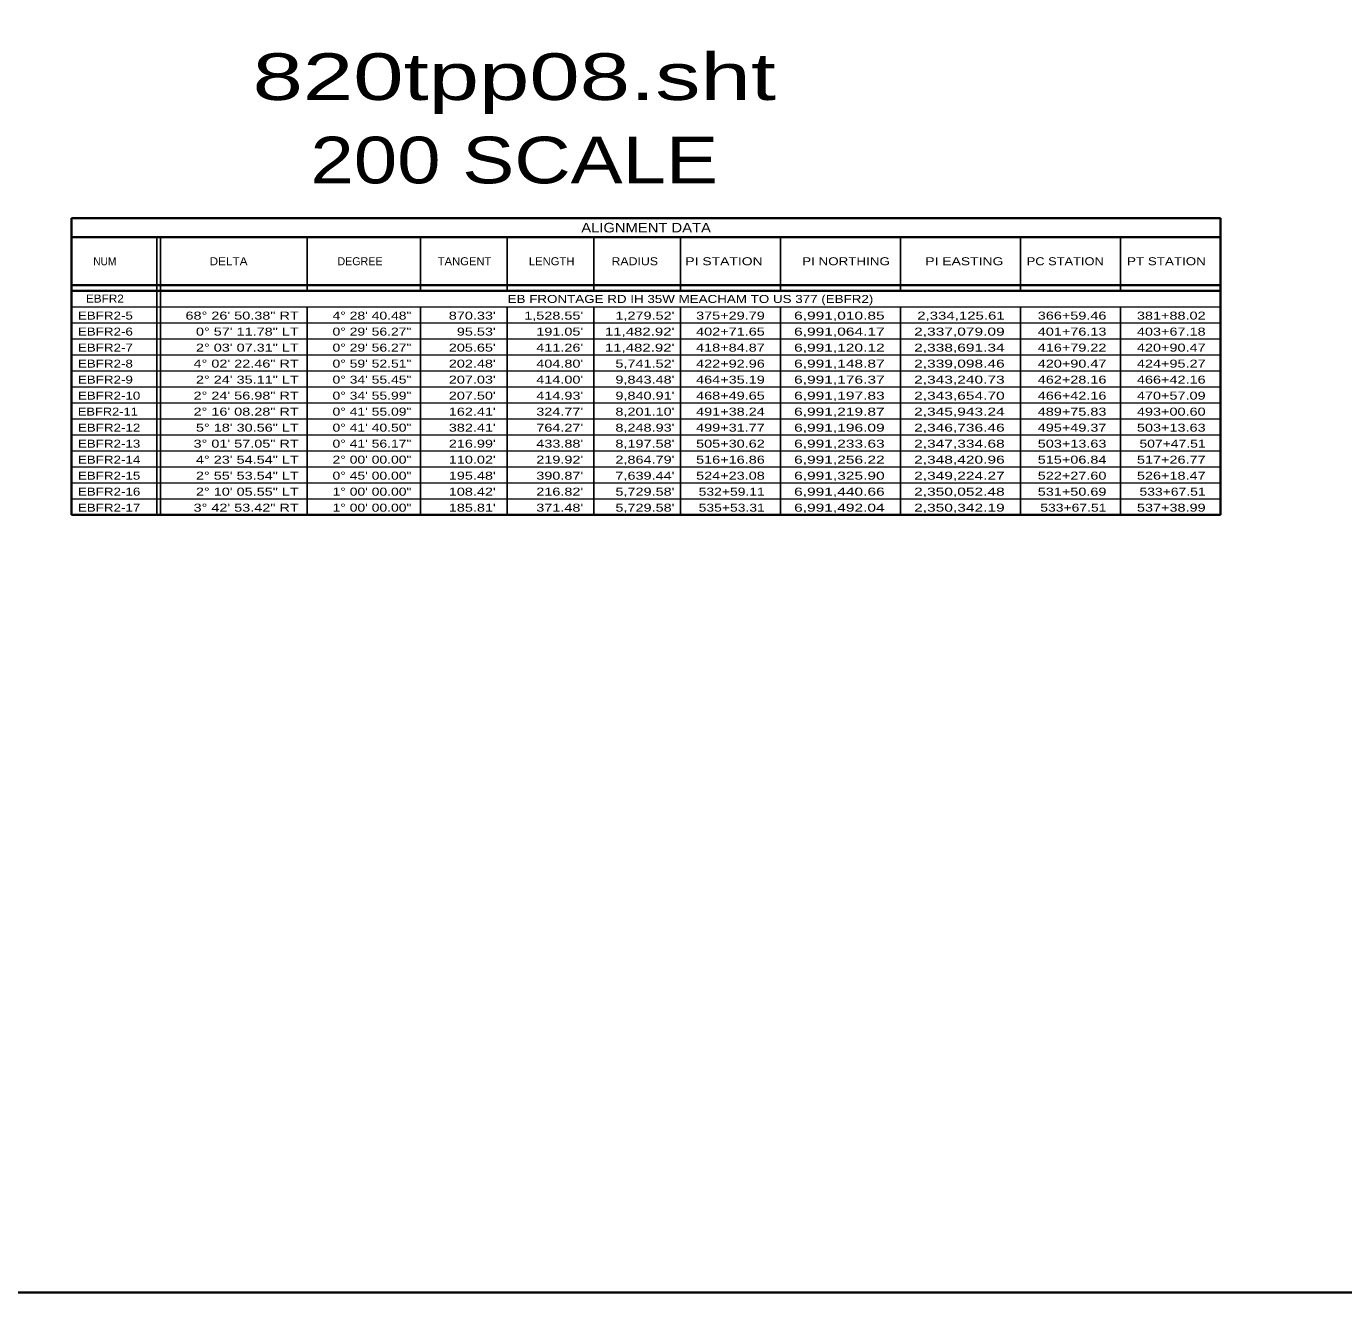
# Model space of a CAD drawing. Extents: x 1953053 to 1967065, y 7363860 to 7371201.
# Drawn here: x 1955866 to 1957841, y 7363860 to 7365759 of the extents above; entities that cross this region are included whole.
import ezdxf
from ezdxf.enums import TextEntityAlignment as Align

# ---------------------------------------------------------------- set-up
doc = ezdxf.new("R2010")
doc.units = 0
doc.header["$LTSCALE"] = 4.8
doc.layers.add('10', color=7, linetype='Continuous')
doc.layers.add('12', color=7, linetype='Continuous', lineweight=25)
doc.layers.add('62', color=7, linetype='Continuous', lineweight=35)

msp = doc.modelspace()

# ---------------------------------------------------------------- linework, layer by layer
at = {"layer": '12', "lineweight": 35}
for p, q in [((1957656.717, 7365471.266), (1955933.385, 7365471.266)), ((1955933.385, 7365471.266), (1955933.385, 7365026.133)), ((1957656.717, 7365026.133), (1957656.717, 7365471.266)), ((1955933.385, 7365442.466), (1957656.717, 7365442.466)), ((1955933.385, 7365370.466), (1957656.717, 7365370.466)), ((1955933.385, 7365362.133), (1957656.717, 7365362.133)), ((1955933.385, 7365026.133), (1957656.717, 7365026.133))]:
    msp.add_line(p, q, dxfattribs=at)
at = {"layer": '12'}
for p, q in [((1956061.23, 7365442.466), (1956061.23, 7365026.133)), ((1956066.717, 7365442.466), (1956066.717, 7365026.133)), ((1956286.717, 7365442.466), (1956286.717, 7365362.133)), ((1956456.717, 7365442.466), (1956456.717, 7365362.133)), ((1956586.717, 7365442.466), (1956586.717, 7365362.133)), ((1956716.717, 7365442.466), (1956716.717, 7365362.133)), ((1956846.717, 7365442.466), (1956846.717, 7365362.133)), ((1956996.717, 7365442.466), (1956996.717, 7365362.133)), ((1957176.717, 7365442.466), (1957176.717, 7365362.133)), ((1957356.717, 7365442.466), (1957356.717, 7365362.133)), ((1957506.717, 7365442.466), (1957506.717, 7365362.133)), ((1956061.23, 7365420.866), (1956061.23, 7365144.913)), ((1956286.717, 7365338.133), (1956286.717, 7365026.133)), ((1956456.717, 7365338.133), (1956456.717, 7365026.133)), ((1956586.717, 7365338.133), (1956586.717, 7365026.133)), ((1956716.717, 7365338.133), (1956716.717, 7365026.133)), ((1956846.717, 7365338.133), (1956846.717, 7365026.133)), ((1956996.717, 7365338.133), (1956996.717, 7365026.133)), ((1957176.717, 7365338.133), (1957176.717, 7365026.133)), ((1957356.717, 7365338.133), (1957356.717, 7365026.133)), ((1957506.717, 7365338.133), (1957506.717, 7365026.133))]:
    msp.add_line(p, q, dxfattribs=at)
at = {"layer": '12', "lineweight": 13}
for p, q in [((1955933.385, 7365338.133), (1957656.717, 7365338.133)), ((1955933.385, 7365314.133), (1957656.717, 7365314.133)), ((1955933.385, 7365290.133), (1957656.717, 7365290.133)), ((1955933.385, 7365266.133), (1957656.717, 7365266.133)), ((1955933.385, 7365242.133), (1957656.717, 7365242.133)), ((1955933.385, 7365218.133), (1957656.717, 7365218.133)), ((1955933.385, 7365194.133), (1957656.717, 7365194.133)), ((1955933.385, 7365170.133), (1957656.717, 7365170.133)), ((1955933.385, 7365146.133), (1957656.717, 7365146.133)), ((1955933.385, 7365122.133), (1957656.717, 7365122.133)), ((1955933.385, 7365098.133), (1957656.717, 7365098.133)), ((1955933.385, 7365074.133), (1957656.717, 7365074.133)), ((1955933.385, 7365050.133), (1957656.717, 7365050.133))]:
    msp.add_line(p, q, dxfattribs=at)
at = {"layer": '62'}
msp.add_lwpolyline([(1953052.784, 7371201.108), (1967065.314, 7371201.108), (1967065.314, 7363859.877), (1953052.784, 7363859.877)], close=True, dxfattribs=at)

# ---------------------------------------------------------------- texts
at = {"layer": '10'}
for s, width, p in [('EBFR2', 1.1, (1955955.056, 7365344.476)), ('EBFR2-5', 1.25, (1955943.006, 7365318.96)), ('EBFR2-6', 1.25, (1955943.006, 7365294.96)), ('EBFR2-7', 1.25, (1955943.006, 7365270.96)), ('EBFR2-8', 1.25, (1955943.006, 7365246.96)), ('EBFR2-9', 1.25, (1955943.006, 7365222.96)), ('EBFR2-10', 1.25, (1955943.006, 7365198.96)), ('EBFR2-11', 1.2, (1955943.006, 7365174.96)), ('EBFR2-12', 1.25, (1955943.006, 7365150.96)), ('EBFR2-13', 1.25, (1955943.006, 7365126.96)), ('EBFR2-14', 1.25, (1955943.006, 7365102.96)), ('EBFR2-15', 1.25, (1955943.006, 7365078.96)), ('EBFR2-16', 1.25, (1955943.006, 7365054.96)), ('EBFR2-17', 1.25, (1955943.006, 7365030.96))]:
    msp.add_text(s, height=12, dxfattribs=dict(at, width=width)).set_placement(p)
at = {"layer": '10', "width": 1.25}
msp.add_text('EB FRONTAGE RD IH 35W MEACHAM TO US 377 (EBFR2)', height=12, dxfattribs=at).set_placement((1956861.717, 7365343.927), align=Align.CENTER)
at = {"layer": '10'}
for s, width, p in [('68° 26\' 50.38" RT', 1.35, (1956274.239, 7365318.96)), ('4° 28\' 40.48"', 1.3, (1956443.234, 7365318.96)), ("870.33'", 1.35, (1956569.644, 7365318.96)), ("1,528.55'", 1.35, (1956700.841, 7365318.96)), ("1,279.52'", 1.35, (1956837.61, 7365318.96)), ('375+29.79', 1.35, (1956973.154, 7365318.96)), ('6,991,010.85', 1.45, (1957152.919, 7365318.96)), ('2,334,125.61', 1.4, (1957332.919, 7365318.96)), ('366+59.46', 1.35, (1957485.497, 7365318.96)), ('381+88.02', 1.35, (1957634.229, 7365318.96)), ('0° 57\' 11.78" LT', 1.35, (1956274.239, 7365294.96)), ('0° 29\' 56.27"', 1.3, (1956443.234, 7365294.96)), ("95.53'", 1.35, (1956569.644, 7365294.96)), ("191.05'", 1.35, (1956700.841, 7365294.96)), ("11,482.92'", 1.4, (1956837.61, 7365294.96)), ('402+71.65', 1.35, (1956973.154, 7365294.96)), ('6,991,064.17', 1.45, (1957152.919, 7365294.96)), ('2,337,079.09', 1.45, (1957332.919, 7365294.96)), ('401+76.13', 1.35, (1957485.497, 7365294.96)), ('403+67.18', 1.35, (1957634.229, 7365294.96)), ('2° 03\' 07.31" LT', 1.35, (1956274.239, 7365270.96)), ('0° 29\' 56.27"', 1.3, (1956443.234, 7365270.96)), ("205.65'", 1.35, (1956569.644, 7365270.96)), ("411.26'", 1.35, (1956700.841, 7365270.96)), ("11,482.92'", 1.4, (1956837.61, 7365270.96)), ('418+84.87', 1.35, (1956973.154, 7365270.96)), ('6,991,120.12', 1.45, (1957152.919, 7365270.96)), ('2,338,691.34', 1.45, (1957332.919, 7365270.96)), ('416+79.22', 1.35, (1957485.497, 7365270.96)), ('420+90.47', 1.35, (1957634.229, 7365270.96)), ('4° 02\' 22.46" RT', 1.35, (1956274.239, 7365246.96)), ('0° 59\' 52.51"', 1.3, (1956443.234, 7365246.96)), ("202.48'", 1.35, (1956569.644, 7365246.96)), ("404.80'", 1.35, (1956700.841, 7365246.96)), ("5,741.52'", 1.35, (1956837.61, 7365246.96)), ('422+92.96', 1.35, (1956973.154, 7365246.96)), ('6,991,148.87', 1.45, (1957152.919, 7365246.96)), ('2,339,098.46', 1.45, (1957332.919, 7365246.96)), ('420+90.47', 1.35, (1957485.497, 7365246.96)), ('424+95.27', 1.35, (1957634.229, 7365246.96)), ('2° 24\' 35.11" LT', 1.35, (1956274.239, 7365222.96)), ('0° 34\' 55.45"', 1.3, (1956443.234, 7365222.96)), ("207.03'", 1.35, (1956569.644, 7365222.96)), ("414.00'", 1.35, (1956700.841, 7365222.96)), ("9,843.48'", 1.35, (1956837.61, 7365222.96)), ('464+35.19', 1.35, (1956973.154, 7365222.96)), ('6,991,176.37', 1.45, (1957152.919, 7365222.96)), ('2,343,240.73', 1.45, (1957332.919, 7365222.96)), ('462+28.16', 1.35, (1957485.497, 7365222.96)), ('466+42.16', 1.35, (1957634.229, 7365222.96)), ('2° 24\' 56.98" RT', 1.35, (1956274.239, 7365198.96)), ('0° 34\' 55.99"', 1.3, (1956443.234, 7365198.96)), ("207.50'", 1.35, (1956569.644, 7365198.96)), ("414.93'", 1.35, (1956700.841, 7365198.96)), ("9,840.91'", 1.35, (1956837.61, 7365198.96)), ('468+49.65', 1.35, (1956973.154, 7365198.96)), ('6,991,197.83', 1.45, (1957152.919, 7365198.96)), ('2,343,654.70', 1.45, (1957332.919, 7365198.96)), ('466+42.16', 1.35, (1957485.497, 7365198.96)), ('470+57.09', 1.35, (1957634.229, 7365198.96)), ('2° 16\' 08.28" RT', 1.35, (1956274.239, 7365174.96)), ('0° 41\' 55.09"', 1.3, (1956443.234, 7365174.96)), ("162.41'", 1.35, (1956569.644, 7365174.96)), ("324.77'", 1.35, (1956700.841, 7365174.96)), ("8,201.10'", 1.35, (1956837.61, 7365174.96)), ('491+38.24', 1.35, (1956973.154, 7365174.96)), ('6,991,219.87', 1.45, (1957152.919, 7365174.96)), ('2,345,943.24', 1.45, (1957332.919, 7365174.96)), ('489+75.83', 1.35, (1957485.497, 7365174.96)), ('493+00.60', 1.35, (1957634.229, 7365174.96)), ('5° 18\' 30.56" LT', 1.35, (1956274.239, 7365150.96)), ('0° 41\' 40.50"', 1.3, (1956443.234, 7365150.96)), ("382.41'", 1.35, (1956569.644, 7365150.96)), ("764.27'", 1.35, (1956700.841, 7365150.96)), ("8,248.93'", 1.35, (1956837.61, 7365150.96)), ('499+31.77', 1.35, (1956973.154, 7365150.96)), ('6,991,196.09', 1.45, (1957152.919, 7365150.96)), ('2,346,736.46', 1.45, (1957332.919, 7365150.96)), ('495+49.37', 1.35, (1957485.497, 7365150.96)), ('503+13.63', 1.35, (1957634.229, 7365150.96)), ('3° 01\' 57.05" RT', 1.35, (1956274.239, 7365126.96)), ('0° 41\' 56.17"', 1.3, (1956443.234, 7365126.96)), ("216.99'", 1.35, (1956569.644, 7365126.96)), ("433.88'", 1.35, (1956700.841, 7365126.96)), ("8,197.58'", 1.35, (1956837.61, 7365126.96)), ('505+30.62', 1.35, (1956973.154, 7365126.96)), ('6,991,233.63', 1.45, (1957152.919, 7365126.96)), ('2,347,334.68', 1.45, (1957332.919, 7365126.96)), ('503+13.63', 1.35, (1957485.497, 7365126.96)), ('507+47.51', 1.3, (1957634.229, 7365126.96)), ('4° 23\' 54.54" LT', 1.35, (1956274.239, 7365102.96)), ('2° 00\' 00.00"', 1.3, (1956443.234, 7365102.96)), ("110.02'", 1.35, (1956569.644, 7365102.96)), ("219.92'", 1.35, (1956700.841, 7365102.96)), ("2,864.79'", 1.35, (1956837.61, 7365102.96)), ('516+16.86', 1.35, (1956973.154, 7365102.96)), ('6,991,256.22', 1.45, (1957152.919, 7365102.96)), ('2,348,420.96', 1.45, (1957332.919, 7365102.96)), ('515+06.84', 1.35, (1957485.497, 7365102.96)), ('517+26.77', 1.35, (1957634.229, 7365102.96)), ('2° 55\' 53.54" LT', 1.35, (1956274.239, 7365078.96)), ('0° 45\' 00.00"', 1.3, (1956443.234, 7365078.96)), ("195.48'", 1.35, (1956569.644, 7365078.96)), ("390.87'", 1.35, (1956700.841, 7365078.96)), ("7,639.44'", 1.35, (1956837.61, 7365078.96)), ('524+23.08', 1.35, (1956973.154, 7365078.96)), ('6,991,325.90', 1.45, (1957152.919, 7365078.96)), ('2,349,224.27', 1.45, (1957332.919, 7365078.96)), ('522+27.60', 1.35, (1957485.497, 7365078.96)), ('526+18.47', 1.35, (1957634.229, 7365078.96)), ('2° 10\' 05.55" LT', 1.35, (1956274.239, 7365054.96)), ('1° 00\' 00.00"', 1.3, (1956443.234, 7365054.96)), ("108.42'", 1.35, (1956569.644, 7365054.96)), ("216.82'", 1.35, (1956700.841, 7365054.96)), ("5,729.58'", 1.35, (1956837.61, 7365054.96)), ('532+59.11', 1.3, (1956973.154, 7365054.96)), ('6,991,440.66', 1.45, (1957152.919, 7365054.96)), ('2,350,052.48', 1.45, (1957332.919, 7365054.96)), ('531+50.69', 1.35, (1957485.497, 7365054.96)), ('533+67.51', 1.3, (1957634.229, 7365054.96)), ('3° 42\' 53.42" RT', 1.35, (1956274.239, 7365030.96)), ('1° 00\' 00.00"', 1.3, (1956443.234, 7365030.96)), ("185.81'", 1.35, (1956569.644, 7365030.96)), ("371.48'", 1.35, (1956700.841, 7365030.96)), ("5,729.58'", 1.35, (1956837.61, 7365030.96)), ('535+53.31', 1.3, (1956973.154, 7365030.96)), ('6,991,492.04', 1.45, (1957152.919, 7365030.96)), ('2,350,342.19', 1.45, (1957332.919, 7365030.96)), ('533+67.51', 1.3, (1957485.497, 7365030.96)), ('537+38.99', 1.35, (1957634.229, 7365030.96))]:
    msp.add_text(s, height=12, dxfattribs=dict(at, width=width)).set_placement(p, align=Align.RIGHT)
at = {"layer": '12'}
for s, height, width, p in [('ALIGNMENT DATA', 14.4, 1.15, (1956795.158, 7365449.665)), ('NUM', 12, 0.95, (1955983.431, 7365400.462)), ('DELTA', 12, 1.1, (1956169.008, 7365400.465)), ('TANGENT', 12, 1.05, (1956522.905, 7365400.465)), ('LENGTH', 12, 1.05, (1956653.54, 7365400.465)), ('RADIUS', 12, 1.15, (1956778.15, 7365400.465)), ('PI STATION', 12, 1.3, (1956911.954, 7365400.465)), ('PI NORTHING', 12, 1.25, (1957095.029, 7365400.465)), ('PI EASTING', 12, 1.3, (1957272.421, 7365400.465)), ('PC STATION', 12, 1.2, (1957423.726, 7365400.465)), ('PT STATION', 12, 1.25, (1957575.497, 7365400.465))]:
    msp.add_text(s, height=height, dxfattribs=dict(at, width=width)).set_placement(p, align=Align.CENTER)
msp.add_text('DEGREE', height=12, dxfattribs=at).set_placement((1956366.094, 7365400.465), align=Align.CENTER)
at = {"layer": '62'}
for s, width, p in [('820tpp08.sht', 1.45, (1956597.441, 7365648.265)), ('200 SCALE', 1.25, (1956597.441, 7365523.265))]:
    msp.add_text(s, height=70, dxfattribs=dict(at, width=width)).set_placement(p, align=Align.CENTER)

doc.saveas('drawing.dxf')
